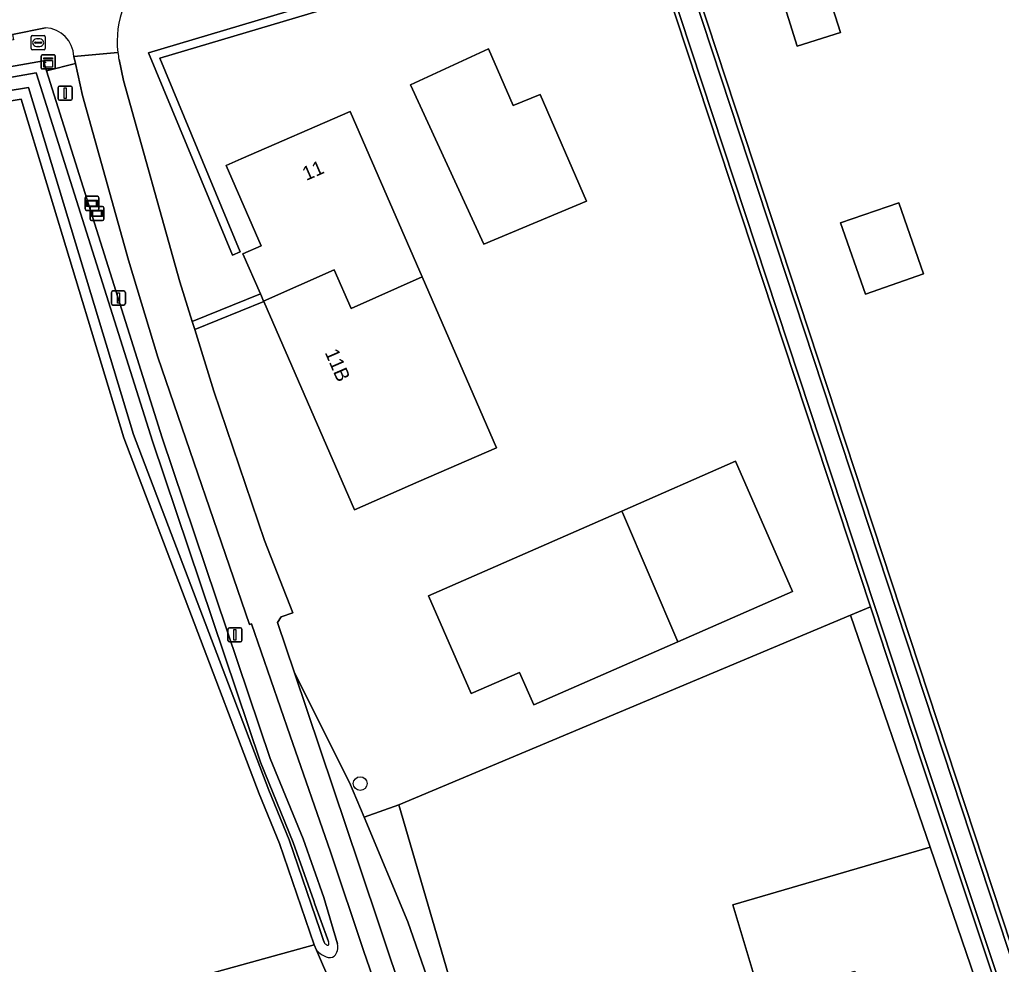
# Model space of a CAD drawing. Extents: x 162510 to 163918, y 388494 to 389774.
# Drawn here: x 163159.5 to 163229.3, y 388912.9 to 388980.1 of the extents above; entities that cross this region are included whole.
import ezdxf

# ---------------------------------------------------------------- set-up
doc = ezdxf.new("R2010")
doc.units = 0
for name, color, linetype in [('IMGEO_Berm_groen', 7, 'Continuous'), ('IMGEO_Boom', 7, 'Continuous'), ('IMGEO_Erf', 7, 'Continuous'), ('IMGEO_Grasland_agrarisch', 7, 'Continuous'), ('IMGEO_Grasland_overig', 7, 'Continuous'), ('IMGEO_Groenvoorziening', 7, 'Continuous'), ('IMGEO_Haag', 7, 'Continuous'), ('IMGEO_Informatiebord', 7, 'Continuous'), ('IMGEO_Kast', 7, 'Continuous'), ('IMGEO_Oever', 7, 'Continuous'), ('IMGEO_Pand', 7, 'Continuous'), ('IMGEO_Pand_nummerreeks', 7, 'Continuous'), ('IMGEO_Rijbaan_lokaal_gesloten', 7, 'Continuous'), ('IMGEO_Rioolput', 7, 'Continuous'), ('IMGEO_Terreindeel_onvherhard', 7, 'Continuous'), ('IMGEO_Verkeersbordpaal', 7, 'Continuous'), ('IMGEO_Waterloop', 7, 'Continuous')]:
    doc.layers.add(name, color=color, linetype=linetype)

msp = doc.modelspace()

# ---------------------------------------------------------------- linework, layer by layer
at = {"layer": 'IMGEO_Berm_groen'}
for points in [[(163161.316, 388979.553), (163158.963, 388979.09), (163159.04, 388978.698), (163155.345, 388977.971), (163142.884, 388975.48), (163127.634, 388972.457), (163124.953, 388971.91), (163123.835, 388971.112), (163123.16, 388970.437), (163122.893, 388969.691), (163125.918, 388970.212), (163125.807, 388970.958), (163161.159, 388977.199)], [(163161.159, 388977.199), (163161.379, 388976.501), (163163.438, 388977.022), (163163.328, 388977.521)], [(163196.277, 388877.868), (163193.583, 388885.565), (163190.814, 388893.467), (163188.492, 388900.413), (163185.957, 388908.078), (163183.975, 388913.824), (163181.599, 388920.906), (163178.735, 388929.17), (163175.983, 388937.13), (163175.831, 388937.091), (163169.301, 388956.116), (163167.229, 388963.023), (163163.944, 388974.74), (163163.438, 388977.022), (163161.379, 388976.501), (163169.621, 388950.367), (163177.299, 388927.553), (163179.642, 388921.834), (163181.123, 388917.659), (163182.1, 388914.357)], [(163180.745, 388913.772), (163180.593, 388913.917), (163182.784, 388908.831), (163182.851, 388908.976), (163182.932, 388909.112)]]:
    msp.add_lwpolyline(points, dxfattribs=at)
msp.add_lwpolyline([(163202.31, 388871.241), (163203.588, 388871.754), (163202.025, 388876.508), (163200.884, 388876.132), (163200.581, 388877.17), (163187.094, 388915.926), (163183.983, 388923.378), (163182.949, 388925.857), (163179.03, 388933.65), (163183.641, 388919.962), (163186.8, 388910.557), (163191.504, 388896.442), (163198.6, 388875.788), (163205.172, 388858.128), (163211.894, 388840.113), (163215.387, 388831.038), (163223.192, 388809.817), (163224.506, 388805.332), (163224.654, 388812.251), (163221.429, 388817.887), (163214.672, 388835.075), (163210.419, 388847.688), (163206.383, 388858.906)], close=True, dxfattribs=at)
for centre, radius, start, end in [((163161.22, 388977.446), 2.109, 2.03522, 87.39806), ((163181.23, 388914.128), 0.899, 314.79729, 14.7484), ((163181.73, 388914.795), 1.42, 226.09325, 252.34496), ((163181.535, 388914.012), 0.617, 247.48534, 302.22655)]:
    msp.add_arc(centre, radius, start, end, dxfattribs=at)
at = {"layer": 'IMGEO_Boom'}
msp.add_circle((163183.712, 388925.766), 0.489, dxfattribs=at)
at = {"layer": 'IMGEO_Erf'}
for points in [[(163205.829, 388987.826), (163237.905, 388890.433), (163295.885, 388909.548), (163303.642, 388886.875), (163348.742, 388900.219), (163350.129, 388900.732), (163351.034, 388900.972), (163360.59, 388903.731), (163362.046, 388904.151), (163355.406, 388924.72), (163354.013, 388929.189), (163350.654, 388931.58), (163341.318, 388928.28), (163332.123, 388924.832), (163319.849, 388920.884), (163315.096, 388934.858), (163309.868, 388940.124), (163304.467, 388955.271), (163299.093, 388954.349), (163292.952, 388972.769), (163296.588, 388975.913), (163313.192, 388984.698)], [(163166.545, 388977.297), (163166.853, 388975.816), (163170.886, 388961.466), (163171.755, 388958.665), (163176.606, 388960.633), (163175.367, 388963.478), (163176.655, 388964.039), (163174.169, 388969.749), (163175.251, 388970.22), (163183.005, 388973.596), (163185.001, 388969.012), (163188.13, 388961.827), (163193.425, 388949.669), (163187.885, 388947.257), (163183.3, 388945.26), (163176.845, 388960.083), (163171.933, 388958.09), (163173.298, 388953.689), (163176.906, 388943.071), (163178.91, 388937.913), (163178.09, 388937.632), (163177.835, 388937.241), (163179.03, 388933.65), (163182.949, 388925.857), (163183.983, 388923.378), (163186.472, 388924.266), (163218.619, 388937.76), (163220.028, 388938.344), (163203.899, 388987.269)]]:
    msp.add_lwpolyline(points, dxfattribs=at)
for points in [[(163219.946, 388983.139), (163216.953, 388982.202), (163217.888, 388979.215), (163214.814, 388978.252), (163212.839, 388984.559), (163215.202, 388985.299), (163218.906, 388986.459)], [(163180.852, 388980.791), (163169.455, 388977.385), (163175.169, 388963.613), (163174.615, 388963.383), (163168.646, 388977.77), (163180.681, 388981.366)], [(163199.83, 388967.229), (163192.508, 388964.164), (163187.29, 388975.499), (163192.838, 388978.069), (163194.608, 388974.03), (163196.515, 388974.802)], [(163223.806, 388962.052), (163219.667, 388960.608), (163217.903, 388965.664), (163222.041, 388967.109)], [(163210.426, 388948.714), (163214.493, 388939.449), (163206.319, 388935.861), (163196.073, 388931.364), (163195.055, 388933.682), (163191.622, 388932.175), (163188.573, 388939.122), (163202.339, 388945.164)], [(163224.28, 388921.243), (163210.234, 388917.13), (163212.225, 388910.494), (163218.924, 388912.412), (163220.41, 388907.224), (163228.154, 388909.937)]]:
    msp.add_lwpolyline(points, close=True, dxfattribs=at)
for centre, radius, start, end in [((163173.086, 388978.611), 6.673, 158.15969, 187.01761), ((163172.791, 388978.58), 6.377, 187.05944, 191.60443)]:
    msp.add_arc(centre, radius, start, end, dxfattribs=at)
at = {"layer": 'IMGEO_Grasland_agrarisch'}
for points in [[(163151.526, 388907.045), (163162.752, 388909.718), (163172.367, 388912.053), (163180.426, 388914.304), (163177.974, 388921.494), (163176.525, 388925.031), (163166.878, 388950.374), (163159.581, 388974.479), (163126.1, 388968.984)], [(163294.567, 388906.947), (163236.766, 388888.053), (163235.758, 388887.75), (163228.154, 388909.937), (163220.41, 388907.224), (163213.711, 388905.306), (163212.225, 388910.494), (163210.234, 388917.13), (163224.28, 388921.243), (163218.619, 388937.76), (163186.472, 388924.266), (163190.147, 388911.649), (163195.262, 388896.963), (163201.697, 388877.506), (163202.025, 388876.508), (163203.588, 388871.754), (163218.206, 388828.934), (163221.192, 388821.645), (163225.664, 388812.896)]]:
    msp.add_lwpolyline(points, dxfattribs=at)
at = {"layer": 'IMGEO_Grasland_overig'}
msp.add_lwpolyline([(163220.028, 388938.344), (163218.619, 388937.76), (163224.28, 388921.243), (163228.154, 388909.937), (163235.758, 388887.75), (163236.766, 388888.053), (163223.616, 388927.461)], close=True, dxfattribs=at)
at = {"layer": 'IMGEO_Groenvoorziening'}
for points in [[(163180.852, 388980.791), (163180.681, 388981.366), (163168.646, 388977.77), (163174.615, 388963.383), (163175.169, 388963.613), (163169.455, 388977.385)], [(163176.845, 388960.083), (163176.835, 388960.106), (163176.683, 388960.456), (163176.606, 388960.633), (163171.755, 388958.665), (163171.844, 388958.377), (163171.933, 388958.09)]]:
    msp.add_lwpolyline(points, close=True, dxfattribs=at)
at = {"layer": 'IMGEO_Haag'}
for points in [[(163180.852, 388980.791), (163180.681, 388981.366), (163168.646, 388977.77), (163174.615, 388963.383), (163175.169, 388963.613), (163169.455, 388977.385)], [(163176.845, 388960.083), (163176.835, 388960.106), (163176.683, 388960.456), (163176.606, 388960.633), (163171.755, 388958.665), (163171.844, 388958.377), (163171.933, 388958.09)]]:
    msp.add_lwpolyline(points, close=True, dxfattribs=at)
at = {"layer": 'IMGEO_Informatiebord'}
for p, q in [((163164.129, 388966.662), (163164.129, 388967.462)), ((163164.129, 388967.462), (163164.129, 388966.662)), ((163164.229, 388967.562), (163165.019, 388967.562)), ((163165.019, 388967.562), (163164.229, 388967.562)), ((163165.119, 388967.462), (163165.119, 388966.662)), ((163165.119, 388966.662), (163165.119, 388967.462)), ((163164.486, 388965.948), (163164.486, 388966.748)), ((163164.486, 388966.748), (163164.486, 388965.948)), ((163164.586, 388966.848), (163165.376, 388966.848)), ((163165.376, 388966.848), (163164.586, 388966.848)), ((163165.476, 388966.748), (163165.476, 388965.948)), ((163165.476, 388965.948), (163165.476, 388966.748)), ((163165.019, 388966.562), (163164.229, 388966.562)), ((163164.229, 388966.562), (163165.019, 388966.562)), ((163165.376, 388965.848), (163164.586, 388965.848)), ((163164.586, 388965.848), (163165.376, 388965.848))]:
    msp.add_line(p, q, dxfattribs=at)
for points in [[(163164.23, 388967.294), (163165.018, 388967.294), (163165.018, 388966.83), (163164.23, 388966.83), (163164.23, 388967.294)], [(163164.295, 388967.229), (163164.295, 388966.895), (163164.953, 388966.895), (163164.953, 388967.229), (163164.295, 388967.229)], [(163164.587, 388966.58), (163165.375, 388966.58), (163165.375, 388966.116), (163164.587, 388966.116), (163164.587, 388966.58)], [(163164.652, 388966.515), (163164.652, 388966.181), (163165.31, 388966.181), (163165.31, 388966.515), (163164.652, 388966.515)]]:
    msp.add_lwpolyline(points, dxfattribs=at)
for centre, start, end in [((163164.229, 388967.462), 90, 180), ((163164.229, 388967.462), 90, 180), ((163165.019, 388967.462), 0, 90), ((163165.019, 388967.462), 360, 90), ((163164.586, 388966.748), 90, 180), ((163164.586, 388966.748), 90, 180), ((163165.376, 388966.748), 0, 90), ((163165.376, 388966.748), 360, 90), ((163164.229, 388966.662), 180, 270), ((163164.229, 388966.662), 180, 270), ((163165.019, 388966.662), 270, 0), ((163165.019, 388966.662), 270, 0), ((163164.586, 388965.948), 180, 270), ((163164.586, 388965.948), 180, 270), ((163165.376, 388965.948), 270, 0), ((163165.376, 388965.948), 270, 0)]:
    msp.add_arc(centre, 0.1, start, end, dxfattribs=at)
at = {"layer": 'IMGEO_Kast'}
for p, q in [((163161.008, 388976.7), (163161.008, 388977.541)), ((163161.008, 388977.541), (163161.008, 388976.7)), ((163161.083, 388977.625), (163161.924, 388977.625)), ((163161.924, 388977.625), (163161.083, 388977.625)), ((163162.008, 388977.55), (163162.008, 388976.709)), ((163162.008, 388976.709), (163162.008, 388977.55)), ((163161.933, 388976.625), (163161.092, 388976.625)), ((163161.092, 388976.625), (163161.933, 388976.625))]:
    msp.add_line(p, q, dxfattribs=at)
for points in [[(163161.203, 388977.415), (163161.803, 388977.415), (163161.803, 388977.33), (163161.203, 388977.33), (163161.203, 388977.415)], [(163161.203, 388977.24), (163161.803, 388977.24), (163161.803, 388976.751), (163161.203, 388976.751), (163161.203, 388977.24)]]:
    msp.add_lwpolyline(points, dxfattribs=at)
msp.add_circle((163161.287, 388977.089), 0.0377, dxfattribs=at)
for centre, start, end in [((163161.086, 388977.547), 92.4484, 184.28452), ((163161.086, 388977.547), 92.4484, 184.28452), ((163161.93, 388977.547), 2.4484, 94.28452), ((163161.93, 388977.547), 2.4484, 94.28452), ((163161.086, 388976.703), 182.4484, 274.28452), ((163161.086, 388976.703), 182.4484, 274.28452), ((163161.93, 388976.703), 272.4484, 4.28452), ((163161.93, 388976.703), 272.4484, 4.28452)]:
    msp.add_arc(centre, 0.0779, start, end, dxfattribs=at)
at = {"layer": 'IMGEO_Oever'}
for points in [[(163205.829, 388987.826), (163226.643, 388995.178), (163226.37, 388996.013), (163226.042, 388997.017), (163203.208, 388989.364), (163203.242, 388989.262), (163203.361, 388988.9), (163203.43, 388988.692), (163203.899, 388987.269), (163220.028, 388938.344), (163223.616, 388927.461), (163236.766, 388888.053), (163294.567, 388906.947), (163302.097, 388885.506), (163302.403, 388884.634), (163389.097, 388910.154)], [(163204.183, 388987.363), (163203.645, 388988.993), (163203.586, 388989.175), (163225.851, 388996.637), (163226.268, 388995.363), (163205.453, 388988.011), (163237.714, 388890.055), (163295.698, 388909.171), (163303.452, 388886.507), (163348.836, 388899.935), (163350.219, 388900.446), (163351.114, 388900.684), (163388.413, 388911.451), (163389.08, 388915.215), (163389.499, 388916.535)], [(163389.217, 388916.637), (163388.789, 388915.287), (163388.151, 388911.687), (163362.046, 388904.151), (163360.59, 388903.731), (163351.034, 388900.972), (163350.129, 388900.732), (163348.742, 388900.219), (163303.642, 388886.875), (163295.885, 388909.548), (163237.905, 388890.433), (163205.829, 388987.826)], [(163389.001, 388910.438), (163302.591, 388885.001), (163302.379, 388885.605), (163294.752, 388907.322), (163236.956, 388888.43), (163223.9, 388927.555), (163220.312, 388938.438), (163204.183, 388987.363)], [(163182.1, 388914.357), (163181.123, 388917.659), (163179.642, 388921.834), (163177.299, 388927.553), (163169.621, 388950.367), (163161.379, 388976.501), (163161.159, 388977.199), (163125.807, 388970.958), (163125.918, 388970.212), (163126.1, 388968.984), (163159.581, 388974.479)], [(163181.149, 388914.477), (163181.106, 388914.605), (163180.866, 388915.308), (163178.668, 388921.754), (163177.214, 388925.303), (163167.579, 388950.613), (163160.102, 388975.315), (163126.722, 388969.836), (163126.65, 388970.321), (163126.645, 388970.354), (163160.648, 388976.357), (163160.673, 388976.278), (163168.917, 388950.138), (163176.605, 388927.294), (163178.95, 388921.57), (163180.417, 388917.433), (163180.49, 388917.18)], [(163159.581, 388974.479), (163166.878, 388950.374), (163176.525, 388925.031), (163177.974, 388921.494), (163180.426, 388914.304), (163180.593, 388913.917), (163180.745, 388913.772)], [(163180.49, 388917.18), (163181.385, 388914.728), (163181.454, 388914.539)]]:
    msp.add_lwpolyline(points, dxfattribs=at)
for centre, radius, start, end in [((163181.542, 388914.659), 0.434, 204.88743, 237.44008), ((163181.397, 388914.461), 0.189, 242.0998, 283.11219), ((163181.417, 388914.34), 0.0672, 290.06958, 3.34329), ((163180.767, 388914.334), 0.717, 0.83819, 16.65414), ((163181.23, 388914.128), 0.899, 314.79729, 14.7484), ((163181.73, 388914.795), 1.42, 226.09325, 252.34496), ((163181.535, 388914.012), 0.617, 247.48534, 302.22655)]:
    msp.add_arc(centre, radius, start, end, dxfattribs=at)
at = {"layer": 'IMGEO_Pand'}
for points in [[(163212.839, 388984.559), (163214.814, 388978.252), (163217.888, 388979.215), (163216.953, 388982.202), (163219.946, 388983.139), (163218.906, 388986.459), (163215.202, 388985.299)], [(163192.508, 388964.164), (163199.83, 388967.229), (163196.515, 388974.802), (163194.608, 388974.03), (163192.838, 388978.069), (163187.29, 388975.499)], [(163185.001, 388969.012), (163183.005, 388973.596), (163175.251, 388970.22), (163174.169, 388969.749), (163176.655, 388964.039), (163175.367, 388963.478), (163176.606, 388960.633), (163176.683, 388960.456), (163176.835, 388960.106), (163181.855, 388962.332), (163183.073, 388959.585), (163188.13, 388961.827)], [(163217.903, 388965.664), (163219.667, 388960.608), (163223.806, 388962.052), (163222.041, 388967.109)], [(163188.13, 388961.827), (163183.073, 388959.585), (163181.855, 388962.332), (163176.835, 388960.106), (163176.845, 388960.083), (163183.3, 388945.26), (163187.885, 388947.257), (163193.425, 388949.669)], [(163202.339, 388945.164), (163202.37, 388945.06), (163206.319, 388935.861), (163214.493, 388939.449), (163210.426, 388948.714)], [(163202.339, 388945.164), (163188.573, 388939.122), (163191.622, 388932.175), (163195.055, 388933.682), (163196.073, 388931.364), (163206.319, 388935.861), (163202.37, 388945.06)]]:
    msp.add_lwpolyline(points, close=True, dxfattribs=at)
at = {"layer": 'IMGEO_Rijbaan_lokaal_gesloten'}
for points in [[(163106.874, 388968.773), (163113.917, 388970.12), (163119.491, 388971.205), (163127.556, 388972.849), (163142.806, 388975.872), (163155.267, 388978.363), (163158.963, 388979.09), (163161.316, 388979.553)], [(163166.463, 388977.796), (163163.328, 388977.521), (163163.438, 388977.022), (163163.944, 388974.74), (163167.229, 388963.023), (163169.301, 388956.116), (163175.831, 388937.091), (163175.983, 388937.13), (163178.735, 388929.17), (163181.599, 388920.906), (163183.975, 388913.824), (163185.957, 388908.078), (163188.492, 388900.413), (163190.814, 388893.467), (163193.583, 388885.565), (163196.277, 388877.868), (163221.552, 388810.028)], [(163163.328, 388977.521), (163166.463, 388977.796)], [(163177.835, 388937.241), (163178.09, 388937.632), (163178.91, 388937.913), (163176.906, 388943.071), (163173.298, 388953.689), (163171.933, 388958.09), (163171.844, 388958.377), (163171.755, 388958.665), (163170.886, 388961.466), (163166.853, 388975.816), (163166.545, 388977.297)], [(163223.192, 388809.817), (163215.387, 388831.038), (163211.894, 388840.113), (163205.172, 388858.128), (163198.6, 388875.788), (163191.504, 388896.442), (163186.8, 388910.557), (163183.641, 388919.962), (163179.03, 388933.65), (163177.835, 388937.241)]]:
    msp.add_lwpolyline(points, dxfattribs=at)
for centre, radius, start, end in [((163173.086, 388978.611), 6.673, 158.15969, 187.01761), ((163161.22, 388977.446), 2.109, 2.03522, 87.39806), ((163172.791, 388978.58), 6.377, 187.05944, 191.60443)]:
    msp.add_arc(centre, radius, start, end, dxfattribs=at)
at = {"layer": 'IMGEO_Rioolput'}
for p, q in [((163160.288, 388978.072), (163160.288, 388978.924)), ((163160.363, 388978.998), (163161.215, 388978.998)), ((163160.776, 388978.778), (163160.801, 388978.778)), ((163161.289, 388978.924), (163161.289, 388978.072)), ((163161.215, 388977.998), (163160.363, 388977.998)), ((163160.547, 388978.492), (163160.547, 388978.504)), ((163160.985, 388978.455), (163160.587, 388978.455)), ((163160.59, 388978.541), (163160.988, 388978.541)), ((163160.799, 388978.218), (163160.774, 388978.218)), ((163161.031, 388978.504), (163161.031, 388978.492))]:
    msp.add_line(p, q, dxfattribs=at)
for points in [[(163160.288, 388978.072), (163160.288, 388978.924)], [(163160.363, 388978.998), (163161.215, 388978.998)], [(163161.289, 388978.924), (163161.289, 388978.072)], [(163161.215, 388977.998), (163160.363, 388977.998)]]:
    msp.add_lwpolyline(points, dxfattribs=at)
for centre, radius, start, end in [((163160.365, 388978.922), 0.0765, 91.55205, 178.44795), ((163160.365, 388978.922), 0.0765, 91.55205, 178.44795), ((163161.213, 388978.922), 0.0765, 1.55205, 88.44795), ((163161.213, 388978.922), 0.0765, 1.55205, 88.44795), ((163160.365, 388978.074), 0.0765, 181.55205, 268.44795), ((163160.365, 388978.074), 0.0765, 181.55205, 268.44795), ((163160.587, 388978.501), 0.0403, 85.87752, 175.75265), ((163160.584, 388978.491), 0.0366, 178.93798, 274.71019), ((163160.988, 388978.498), 0.043, 264.86636, 352.45326), ((163160.992, 388978.503), 0.0386, 1.73085, 96.63898), ((163161.213, 388978.074), 0.0765, 271.55205, 358.44795), ((163161.213, 388978.074), 0.0765, 271.55205, 358.44795)]:
    msp.add_arc(centre, radius, start, end, dxfattribs=at)
for centre, major_axis, ratio, start_param, end_param in [((163160.775, 388978.498), (-0.387, 0.002), 0.722429, 4.712389, 7.853982), ((163160.8, 388978.498), (-0.39, 0.002), 0.717154, 1.570796, 4.712389)]:
    msp.add_ellipse(centre, major_axis=major_axis, ratio=ratio, start_param=start_param, end_param=end_param, dxfattribs=at)
at = {"layer": 'IMGEO_Terreindeel_onvherhard'}
msp.add_lwpolyline([(163180.593, 388913.917), (163180.426, 388914.304), (163172.367, 388912.053), (163162.752, 388909.718), (163151.526, 388907.045), (163140.418, 388904.937), (163110.42, 388899.793), (163054.783, 388897.65), (163054.882, 388896.663), (163091.263, 388897.242), (163103.157, 388898.158), (163103.331, 388895.285), (163150.535, 388902.642), (163156.815, 388904.324), (163166.01, 388906.454), (163176.02, 388908.577), (163181.742, 388908.519), (163182.862, 388908.649), (163182.784, 388908.831)], close=True, dxfattribs=at)
at = {"layer": 'IMGEO_Verkeersbordpaal'}
for p, q in [((163162.22, 388974.508), (163162.22, 388975.308)), ((163162.22, 388975.308), (163162.22, 388974.508)), ((163162.32, 388975.408), (163163.11, 388975.408)), ((163163.11, 388975.408), (163162.32, 388975.408)), ((163163.21, 388975.308), (163163.21, 388974.508)), ((163163.21, 388974.508), (163163.21, 388975.308)), ((163163.11, 388974.408), (163162.32, 388974.408)), ((163162.32, 388974.408), (163163.11, 388974.408)), ((163166.006, 388959.928), (163166.006, 388960.728)), ((163166.006, 388960.728), (163166.006, 388959.928)), ((163166.106, 388960.828), (163166.896, 388960.828)), ((163166.896, 388960.828), (163166.106, 388960.828)), ((163166.996, 388960.728), (163166.996, 388959.928)), ((163166.996, 388959.928), (163166.996, 388960.728)), ((163166.896, 388959.828), (163166.106, 388959.828)), ((163166.106, 388959.828), (163166.896, 388959.828)), ((163174.299, 388935.956), (163174.299, 388936.756)), ((163174.299, 388936.756), (163174.299, 388935.956)), ((163174.399, 388936.856), (163175.189, 388936.856)), ((163175.189, 388936.856), (163174.399, 388936.856)), ((163175.289, 388936.756), (163175.289, 388935.956)), ((163175.289, 388935.956), (163175.289, 388936.756)), ((163175.189, 388935.856), (163174.399, 388935.856)), ((163174.399, 388935.856), (163175.189, 388935.856))]:
    msp.add_line(p, q, dxfattribs=at)
for points in [[(163162.64, 388975.283), (163162.79, 388975.283), (163162.79, 388974.533), (163162.64, 388974.533), (163162.64, 388975.283)], [(163166.426, 388960.703), (163166.576, 388960.703), (163166.576, 388959.953), (163166.426, 388959.953), (163166.426, 388960.703)], [(163174.719, 388936.731), (163174.869, 388936.731), (163174.869, 388935.981), (163174.719, 388935.981), (163174.719, 388936.731)]]:
    msp.add_lwpolyline(points, dxfattribs=at)
for centre, start, end in [((163162.32, 388975.308), 90, 180), ((163162.32, 388975.308), 90, 180), ((163163.11, 388975.308), 0, 90), ((163163.11, 388975.308), 360, 90), ((163162.32, 388974.508), 180, 270), ((163162.32, 388974.508), 180, 270), ((163163.11, 388974.508), 270, 0), ((163163.11, 388974.508), 270, 0), ((163166.106, 388960.728), 90, 180), ((163166.106, 388960.728), 90, 180), ((163166.896, 388960.728), 0, 90), ((163166.896, 388960.728), 360, 90), ((163166.106, 388959.928), 180, 270), ((163166.106, 388959.928), 180, 270), ((163166.896, 388959.928), 270, 0), ((163166.896, 388959.928), 270, 0), ((163174.399, 388936.756), 90, 180), ((163174.399, 388936.756), 90, 180), ((163175.189, 388936.756), 0, 90), ((163175.189, 388936.756), 360, 90), ((163174.399, 388935.956), 180, 270), ((163174.399, 388935.956), 180, 270), ((163175.189, 388935.956), 270, 0), ((163175.189, 388935.956), 270, 0)]:
    msp.add_arc(centre, 0.1, start, end, dxfattribs=at)
at = {"layer": 'IMGEO_Waterloop'}
for points in [[(163389.499, 388916.535), (163389.08, 388915.215), (163388.413, 388911.451), (163351.114, 388900.684), (163350.219, 388900.446), (163348.836, 388899.935), (163303.452, 388886.507), (163295.698, 388909.171), (163237.714, 388890.055), (163205.453, 388988.011), (163226.268, 388995.363), (163225.851, 388996.637), (163203.586, 388989.175), (163203.645, 388988.993), (163204.183, 388987.363), (163220.312, 388938.438), (163223.9, 388927.555), (163236.956, 388888.43), (163294.752, 388907.322), (163302.379, 388885.605), (163302.591, 388885.001), (163389.001, 388910.438)], [(163181.454, 388914.539), (163181.385, 388914.728), (163180.49, 388917.18), (163180.417, 388917.433), (163178.95, 388921.57), (163176.605, 388927.294), (163168.917, 388950.138), (163160.673, 388976.278), (163160.648, 388976.357), (163126.645, 388970.354), (163126.65, 388970.321), (163126.722, 388969.836), (163160.102, 388975.315), (163167.579, 388950.613), (163177.214, 388925.303), (163178.668, 388921.754), (163180.866, 388915.308)], [(163180.866, 388915.308), (163181.106, 388914.605), (163181.149, 388914.477)]]:
    msp.add_lwpolyline(points, dxfattribs=at)
msp.add_lwpolyline([(163195.262, 388896.963), (163190.147, 388911.649), (163186.472, 388924.266), (163183.983, 388923.378), (163187.094, 388915.926), (163200.581, 388877.17), (163200.884, 388876.132), (163202.025, 388876.508), (163201.697, 388877.506)], close=True, dxfattribs=at)
for centre, radius, start, end in [((163181.542, 388914.659), 0.434, 204.88743, 237.44008), ((163181.397, 388914.461), 0.189, 242.0998, 283.11219), ((163181.417, 388914.34), 0.0672, 290.06958, 3.34329), ((163180.767, 388914.334), 0.717, 0.83819, 16.65414)]:
    msp.add_arc(centre, radius, start, end, dxfattribs=at)

# ---------------------------------------------------------------- texts
at = {"layer": 'IMGEO_Pand_nummerreeks'}
for s, rotation, p in [('11', 23.52565, (163179.868, 388968.652)), ('11B', 293.53117, (163181.175, 388956.451))]:
    msp.add_text(s, height=1, rotation=rotation, dxfattribs=at).set_placement(p)

doc.saveas('drawing.dxf')
